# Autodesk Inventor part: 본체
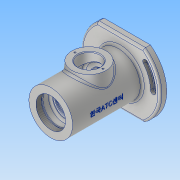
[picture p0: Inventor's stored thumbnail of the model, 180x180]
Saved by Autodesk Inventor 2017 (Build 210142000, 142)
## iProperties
Part Number: 본체
Material: 알루미늄 6061
Document SubType Name: Modeling
Designer: MRC
Density: 2.7 g/cm^3
Appearance: 알루미늄 - 평지
Mass: 689.243 g
Surface Area: 620.752 cm^2
Volume: 255.275 cm^3
Author: MRC
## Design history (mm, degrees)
sketch "스케치1"
  geometry: C1 r 32 at (0, 0); 1 further point
  constraints: 1 centre point, 1 coincident
  dimensions: "d0" = 64 diameter of C1
extrude "돌출1" new body sketch "스케치1" stored distance "d1" = 102; taper "d2" = 0 deg
sketch "스케치2"
  geometry: C1 r 58 at (0, 0); 1 further point
  constraints: 1 centre point, 1 coincident
  dimensions: "d3" = 116 diameter of C1
extrude "돌출2" join sketch "스케치2" distance "d4" = 10; taper "d5" = 0 deg
sketch "스케치3"
  geometry: C1 r 36 at (0, 0); 1 further point
  constraints: 1 centre point, 1 coincident
  dimensions: "d6" = 72 diameter of C1
extrude "돌출3" join sketch "스케치3" distance "d7" = 3; taper "d8" = 0 deg
sketch "스케치4"
  geometry: L1 (-47, -33.985)-(-47, 33.985); L2 (47, -33.985)-(47, 33.985); A1 r 58 centre (0, 0) between (-47, -33.985) and (-47, 33.985) reference; 1 further point
  constraints: 4 end point, 4 point on circle, 2 vertical
  dimensions: "d9" = 94 distance between parallel lines of L2 L1; "d10" = 47 distance from line of point (0, 0) L1
extrude "돌출4" cut sketch "스케치4" distance "d11" = 31.25; taper "d12" = 0 deg
node "작업 평면1"
sketch "스케치5"
  geometry: L1 (32, 51)-(-32, 51) reference; C1 r 25 at (0, -5); 1 further point
  constraints: 1 centre point, 1 vertical alignment
  dimensions: "d14" = 50 diameter of C1; "d15" = 56 distance from line of L1 C1.centre
extrude "돌출5" join sketch "스케치5" stored distance "d16" = 31.25; taper "d17" = 5 deg
sketch "스케치7"
  geometry: 2 further points
  constraints: 1 coincident
hole "구멍1" sketch "스케치7" at (0, 0) diameter "d20" = 43.376; stored, may be unused: countersink angle "d24" = 90 deg, drill point angle "d26" = 0 deg; dims "d21" = 90, "d22" = 4, "d23" = 2, "d25" = 8
sketch "스케치8"
  geometry: L1 (32, 51)-(-32, 51) reference; L2 (-36, -64)-(36, -64) reference; L3 (21.688, 43)-(-21.688, 43) reference; L4 (0, 43)-(0, -64); L5 (0, 43)-(-24, 43); L6 (-24, 43)-(-24, 40); L7 (-24, 40)-(-22.5, 40); L8 (-22.5, 40)-(-22.5, 29); L9 (-22.5, 29)-(-17.5, 29); L10 (-17.5, 29)-(-17.5, 26.75); L11 (-17.5, 26.75)-(-18.5, 26.75); L12 (-18.5, 26.75)-(-18.5, 25); L13 (-18.5, 25)-(-17.5, 25); L14 (-17.5, 25)-(-17.5, 14); L15 (-17.5, 14)-(-27, 14); L16 (-27, 14)-(-27, -24); L17 (-27, -24)-(-17.5, -24); L18 (-17.5, -24)-(-17.5, -35); L19 (-17.5, -35)-(-15, -35); L20 (-15, -35)-(-15, -40); L21 (-15, -40)-(-11, -40); L22 (-11, -40)-(-11, -42.7); L23 (-11, -42.7)-(-15, -42.7); L24 (-15, -42.7)-(-15, -50); L25 (-30, -64)-(0, -64); L26 (-15, -50)-(-20, -50); L27 (-32, -51)-(32, -51) reference; L28 (-20, -50)-(-30, -64); 1 further point
  constraints: 48 end point, 18 perpendicular, 4 point on line, 2 midpoint, 1 horizontal, 1 parallel
  dimensions: "d27" = 48 diameter of L6 L4; "d28" = 45 diameter of L8 L4; "d29" = 35 diameter of L10 L4; "d30" = 37 diameter of L12 L4; "d31" = 54 diameter of L16 L4; "d32" = 35 diameter of L18 L4; "d33" = 30 diameter of L20 L4; "d34" = 22 diameter of L22 L4; "d35" = 30 diameter of L24 L4; "d36" = 60 diameter of L25.start L4; "d37" = 3 distance of L5.end L6.end; "d38" = 22 distance between parallel lines of L9 L1; "d40" = 4 distance between parallel lines of L13 L9; "d41" = 1.75 distance of L11.end L12.end; "d42" = 11 distance between parallel lines of L15 L13; "d43" = 38 distance of L15.end L16.end; "d44" = 11 distance of L17.end L18.end; "d45" = 5 distance of L19.end L20.end; "d46" = 14 distance from line of L2 L24.end; "d47" = 7.3 distance of L23.end L24.end; "d107" = 40 diameter of L26.end L4
revolve "회전1" sketch "스케치8" stored, may be unused: angle "d48" = 90 deg
sketch "스케치9"
  geometry: C1 r 25 at (0, 0) reference; C2 r 16 at (0, 0); 1 further point
  constraints: 1 centre point, 1 coincident
  dimensions: "d49" = 32 diameter of C2
extrude "돌출6" cut sketch "스케치9" distance "d50" = 39; taper "d51" = 0 deg
sketch "스케치10"
  geometry: C1 r 16 at (0, 0) reference; A1 r 20.5 centre (0, 0) between (0, 20.5) and (0, -20.5); 1 further point
  constraints: 2 point on circle, 2 vertical alignment, 1 centre point, 1 coincident
  dimensions: "d52" = 41 diameter of A1
hole "구멍2" sketch "스케치10" at (0, 20.5), (0, -20.5) diameter "d53" = 2.459; stored, may be unused: countersink angle "d57" = 90 deg, drill point angle "d59" = 118 deg; dims "d54" = 6, "d55" = 4, "d56" = 2, "d58" = 8
sketch "스케치13"
  geometry: L1 (0, 0)-(30.854, -36.77); L2 (0, 0)-(0, -48); L3 (0, 0)-(-30.854, 36.77); A1 r 48 centre (0, 0) between (30.854, -36.77) and (0, -48); 3 further points
  constraints: 6 end point, 3 coincident, 3 point on circle, 1 centre point, 1 vertical
  dimensions: "d71" = 96 diameter of A1; "d72" = 40 deg angle of L2 L1; "d73" = 40 deg angle of L3 L2
hole "구멍4" sketch "스케치13" at (-30.854, 36.77), (30.854, -36.77) diameter "d74" = 8; stored, may be unused: countersink angle "d78" = 90 deg, drill point angle "d80" = 118 deg; dims "d75" = 6, "d76" = 8, "d77" = 4.4, "d79" = 8
sketch "스케치14"
  geometry: L1 (-47, -33.985)-(-47, 33.985) reference; L2 (47, 33.985)-(47, -33.985) reference; C1 r 32 at (0, 0) reference; C2 r 20.714 at (0, 0) reference; A1 r 4 centre (-30.854, 36.77) between (-28.283, 33.706) and (-33.425, 39.834) reference; A2 r 4 centre (30.854, -36.77) between (28.283, -33.706) and (33.425, -39.834) reference; A3 r 58 centre (0, 0) between (47, 33.985) and (-47, 33.985) reference; A4 r 58 centre (0, 0) between (-47, -33.985) and (47, -33.985) reference; A5 r 48 centre (0, 0) between (30.854, -36.77) and (0, 48); A6 r 44 centre (0, 0) between (0, 44) and (-28.283, 33.706); A7 r 52 centre (0, 0) between (47, 22.249) and (0, 52); A8 r 4 centre (0, 48) between (0, 52) and (0, 44); A9 r 4 centre (0, -48) between (0, -44) and (0, -52); A10 r 52 centre (0, 0) between (47, -22.249) and (47, 22.249); A11 r 52 centre (0, 0) between (0, 52) and (-33.425, 39.834); A12 r 44 centre (0, 0) between (28.283, -33.706) and (0, 44); A13 r 44 centre (0, 0) between (0, -44) and (28.283, -33.706); A14 r 44 centre (0, 0) between (-28.283, 33.706) and (0, -44); A15 r 52 centre (0, 0) between (-47, 22.249) and (-47, -22.249); A16 r 52 centre (0, 0) between (-47, -22.249) and (0, -52); A17 r 52 centre (0, 0) between (0, -52) and (33.425, -39.834); A18 r 52 centre (0, 0) between (-33.425, 39.834) and (-47, 22.249); A19 r 52 centre (0, 0) between (33.425, -39.834) and (47, -22.249); 1 further point
  constraints: 35 point on circle, 15 centre point, 4 point on line, 4 tangent, 3 coincident, 2 vertical alignment
extrude "돌출7" cut sketch "스케치14" distance "d81" = 4.4; taper "d82" = 0 deg
sketch "스케치15"
  geometry: L1 (-47, -33.985)-(-47, 33.985) reference; L2 (47, 33.985)-(47, -33.985) reference; C1 r 23.857 at (0, 0) reference; A1 r 44 centre (0, 0) between (0, 44) and (-28.283, 33.706) reference; A2 r 4 centre (0, 48) between (0, 44) and (0, 52) reference; A3 r 52 centre (0, 0) between (0, 52) and (-33.425, 39.834) reference; A4 r 4 centre (-30.854, 36.77) between (-28.283, 33.706) and (-33.425, 39.834) reference; A5 r 4 centre (-30.854, 36.77) between (-33.425, 39.834) and (-28.283, 33.706) reference; A6 r 4 centre (0, -48) between (0, -44) and (0, -52) reference; A7 r 52 centre (0, 0) between (0, -52) and (33.425, -39.834) reference; A8 r 4 centre (30.854, -36.77) between (33.425, -39.834) and (28.283, -33.706) reference; A9 r 44 centre (0, 0) between (0, -44) and (28.283, -33.706) reference; A10 r 4 centre (30.854, -36.77) between (28.283, -33.706) and (33.425, -39.834) reference; A11 r 58 centre (0, 0) between (47, 33.985) and (-47, 33.985) reference; A12 r 58 centre (0, 0) between (-47, -33.985) and (47, -33.985) reference; A13 r 2.25 centre (0, 48) between (0, 50.25) and (0, 45.75); A14 r 2.25 centre (0, -48) between (0, -45.75) and (0, -50.25); A15 r 45.75 centre (0, 0) between (3.227, 45.636) and (0, 45.75); A16 r 50.25 centre (0, 0) between (3.382, 50.136) and (0, 50.25); A17 r 50.25 centre (0, 0) between (47, 17.778) and (3.382, 50.136); A18 r 50.25 centre (0, 0) between (47, -17.778) and (47, 17.778); A19 r 50.25 centre (0, 0) between (34.818, -36.233) and (47, -17.778); A20 r 45.75 centre (0, 0) between (31.806, -32.885) and (3.227, 45.636); A21 r 45.75 centre (0, 0) between (-26.862, 37.033) and (0, -45.75); A22 r 50.25 centre (0, 0) between (-29.636, 40.58) and (0, -50.25); A23 r 45.75 centre (0, 0) between (0, -45.75) and (26.862, -37.033); A24 r 50.25 centre (0, 0) between (0, -50.25) and (29.636, -40.58); A25 r 45.75 centre (0, 0) between (26.862, -37.033) and (31.806, -32.885); A26 r 50.25 centre (0, 0) between (29.636, -40.58) and (34.818, -36.233); A27 r 50.25 centre (0, 0) between (0, 50.25) and (-29.636, 40.58); A28 r 45.75 centre (0, 0) between (0, 45.75) and (-26.862, 37.033); 1 further point
  constraints: 40 point on circle, 16 centre point, 4 coincident, 2 point on line, 2 tangent
  dimensions: "d83" = 4.5 diameter of A13; "d84" = 4.5 diameter of A14
extrude "돌출8" cut sketch "스케치15" stored distance "d85" = 4.4; taper "d86" = 0 deg
fillet "모깎기1" dims "d87" = 0.6
fillet "모깎기2" dims "d88" = 0.5
chamfer "모따기1" distance "d89" = 0.7; stored, may be unused: second distance "d90" = 2, angle "d91" = 30 deg
chamfer "모따기2" distance "d92" = 1; stored, may be unused: second distance "d93" = 2, angle "d94" = 30 deg
fillet "모깎기3" dims "d95" = 3
fillet "모깎기4" dims "d96" = 3
fillet "모깎기5" dims "d97" = 3
chamfer "모따기3" distance "d98" = 1; stored, may be unused: second distance "d99" = 2, angle "d100" = 30 deg
fillet "모깎기6" dims "d101" = 3
node "작업 평면3"
sketch "스케치16"
  geometry: L1 (-47, -61)-(47, -61) reference; 2 further points
  constraints: 1 other
  dimensions: "d103" = 62 distance from line of L1 point (0, 1); "d104" = 0 horizontal distance of point (0, 0) point (0, 1)
feature "엠보싱1" sketch "스케치16" dims "d9" = 94, "d105" = 0.5, "d106" = 0
fillet "모깎기7" dims "d108" = 3
chamfer "모따기4" distance "d109" = 1; stored, may be unused: second distance "d110" = 2, angle "d111" = 30 deg
chamfer "모따기5" distance "d112" = 1; stored, may be unused: second distance "d113" = 2, angle "d114" = 30 deg
node "솔리드1"
node "절단 모서리 투영1"
node "절단 모서리 투영2"
other parameters: "d13" = 38, "d102" = -78.25
